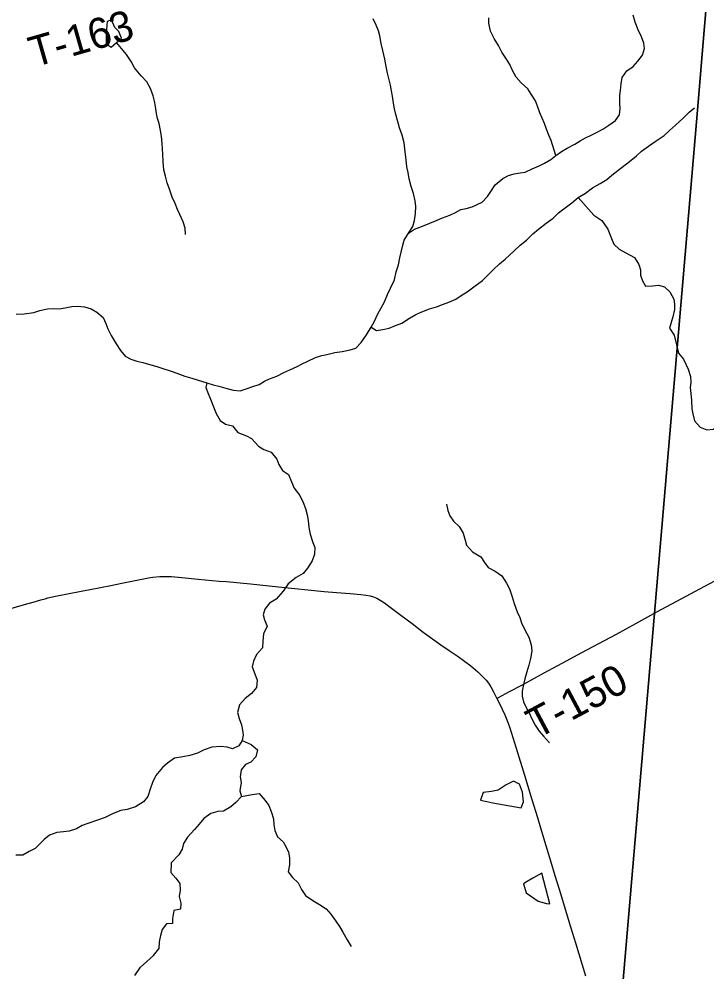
# Model space of a CAD drawing. Extents: x 0 to 1101, y 0 to 440.
# Drawn here: x 846.422 to 847.707, y 377.265 to 379.047 of the extents above; entities that cross this region are included whole.
import ezdxf

# ---------------------------------------------------------------- set-up
doc = ezdxf.new("R2010")
doc.units = 0
for name, color, linetype in [('GM_X_County_Road', 7, 'Continuous'), ('GM_X_Minor_Lake', 7, 'Continuous'), ('GM_X_Minor_River', 7, 'Continuous'), ('GM_X_State_Route', 7, 'Continuous'), ('GM_X_Township_Road', 7, 'Continuous'), ('GM_X_Township_Road_Text', 7, 'Continuous')]:
    doc.layers.add(name, color=color, linetype=linetype)

msp = doc.modelspace()

# ---------------------------------------------------------------- linework, layer by layer
at = {"layer": 'GM_X_County_Road'}
msp.add_lwpolyline([(847.5335, 377.0456), (847.6089, 377.9284), (847.6897, 378.8763), (847.7828, 379.9871), (847.8653, 380.9722), (847.896, 381.3391), (846.8323, 381.427), (846.7789, 381.4314), (846.7617, 381.4329), (846.7534, 381.4335), (845.8327, 381.5116), (845.7218, 381.5239), (845.7047, 381.5258), (845.3492, 381.569), (845.0655, 381.6042), (845.008, 381.6114), (844.8229, 381.6343), (844.8107, 381.6358), (844.7738, 381.6404), (844.7118, 381.648), (844.0658, 381.7282)], dxfattribs=at)
msp.add_lwpolyline([(850.9258, 375.8797), (850.9258, 381.1617), (850.8488, 381.1661), (850.84, 381.1666), (850.8316, 381.167), (850.794, 381.1689), (850.7928, 381.169), (849.9699, 381.2155), (849.9584, 381.2161), (849.5879, 381.237), (848.2076, 381.3203), (847.9626, 381.3347), (847.896, 381.3391), (847.8653, 380.9722), (847.7828, 379.9871), (847.6897, 378.8763), (847.6089, 377.9284), (847.5335, 377.0456), (847.5303, 377.0082), (847.4662, 376.2566), (847.7946, 376.221), (849.0627, 376.0925), (849.9034, 375.9956), (850.1463, 375.9688)], close=True, dxfattribs=at)
at = {"layer": 'GM_X_Minor_Lake'}
for points in [[(846.613, 379.0107), (846.6082, 379.0233), (846.6008, 379.031), (846.5945, 379.0452), (846.5861, 379.0419), (846.5843, 379.0195), (846.5844, 379.0002), (846.5938, 378.9943)], [(846.5938, 378.9943), (846.613, 379.0107)], [(847.3604, 377.5717), (847.3644, 377.5831), (847.3627, 377.6013), (847.3569, 377.6162), (847.3456, 377.6217), (847.3318, 377.6146), (847.3169, 377.6046), (847.3048, 377.6025), (847.2892, 377.6004), (847.2841, 377.5861), (847.2958, 377.5837), (847.3071, 377.5808)], [(847.3071, 377.5808), (847.3604, 377.5717)], [(847.3985, 377.4498), (847.3817, 377.4405), (847.3714, 377.4342), (847.3648, 377.4294), (847.3692, 377.4127), (847.3917, 377.3975), (847.4075, 377.3931), (847.4136, 377.3923)], [(847.4136, 377.3923), (847.3985, 377.4498)]]:
    msp.add_lwpolyline(points, dxfattribs=at)
at = {"layer": 'GM_X_Minor_River'}
for points in [[(847.5446, 378.9039), (847.5455, 378.9133), (847.5468, 378.9258), (847.5492, 378.9372), (847.5577, 378.9496), (847.5696, 378.9581), (847.5781, 378.9679), (847.587, 378.9792), (847.5906, 378.9916), (847.5896, 379.0019), (847.5852, 379.0133), (847.5785, 379.0267), (847.5731, 379.0408), (847.5695, 379.0541)], [(847.1498, 378.6461), (847.1579, 378.6585), (847.1607, 378.6699), (847.1625, 378.6831), (847.163, 378.6964), (847.162, 378.7071), (847.1588, 378.7204), (847.1548, 378.7333), (847.1509, 378.7482), (847.1488, 378.76), (847.1466, 378.7703), (847.1449, 378.7836), (847.1436, 378.7987), (847.1412, 378.8155), (847.138, 378.8296), (847.1329, 378.8433), (847.1289, 378.857), (847.1257, 378.8681), (847.1232, 378.8787), (847.1218, 378.8897), (847.1197, 378.9027), (847.118, 378.9126), (847.1158, 378.9228), (847.1126, 378.9358), (847.1105, 378.9457), (847.108, 378.9578), (847.1055, 378.9719), (847.1016, 378.9879), (847.0987, 379.0008), (847.0959, 379.0153), (847.0934, 379.0248), (847.0894, 379.0355), (847.0835, 379.0474)], [(847.4251, 378.7917), (847.4164, 378.8199), (847.412, 378.8299), (847.4072, 378.8406), (847.4036, 378.8512), (847.3952, 378.8715), (847.3908, 378.884), (847.3868, 378.8936), (847.379, 378.9062), (847.3723, 378.9165), (847.3603, 378.9273), (847.3506, 378.9381), (847.3436, 378.9519), (847.3389, 378.9618), (847.3326, 378.9717), (847.324, 378.9848), (847.3177, 378.997), (847.3096, 379.0104), (847.3026, 379.0241), (847.2998, 379.039), (847.2999, 379.0488)], [(846.7329, 378.6441), (846.7319, 378.6555), (846.7286, 378.6673), (846.722, 378.681), (846.718, 378.6906), (846.7136, 378.702), (846.7077, 378.7139), (846.7026, 378.7287), (846.6986, 378.7405), (846.6954, 378.7531), (846.6921, 378.7645), (846.6908, 378.7801), (846.6906, 378.7938), (846.69, 378.804), (846.689, 378.8143), (846.6877, 378.828), (846.686, 378.8386), (846.6835, 378.8512), (846.6802, 378.8607), (846.6788, 378.8702), (846.6764, 378.8831), (846.675, 378.893), (846.6725, 378.9029), (846.6674, 378.9166), (846.6604, 378.9296), (846.6499, 378.9404), (846.6372, 378.9554), (846.6313, 378.9672), (846.6224, 378.9803), (846.604, 379.003)], [(846.5437, 378.5083), (846.5565, 378.5047), (846.5671, 378.4984), (846.5791, 378.4884), (846.5838, 378.4777), (846.5878, 378.4674), (846.5941, 378.4548), (846.6034, 378.4395), (846.6112, 378.4269), (846.6201, 378.4165), (846.6306, 378.411), (846.6416, 378.4071), (846.6529, 378.4043), (846.6635, 378.4011), (846.6793, 378.3971), (846.6903, 378.3935), (846.7042, 378.3891), (846.7167, 378.3844), (846.7318, 378.3789), (846.7446, 378.3749), (846.7544, 378.3721), (846.7729, 378.3665), (846.7842, 378.363), (846.7952, 378.3602), (846.808, 378.3562), (846.8216, 378.353), (846.8352, 378.3512), (846.8478, 378.3556), (846.8584, 378.3596), (846.8702, 378.3636), (846.8802, 378.3696), (846.8897, 378.374), (846.9034, 378.3791), (846.9164, 378.3858), (846.9279, 378.3909), (846.9412, 378.3972), (846.9508, 378.402), (846.9615, 378.4071), (846.9756, 378.4138), (846.9874, 378.4178), (846.9969, 378.4195), (847.0121, 378.4235), (847.0254, 378.4252), (847.0406, 378.428), (847.0509, 378.4313), (847.0609, 378.4418), (847.0709, 378.456), (847.0798, 378.4707), (847.0857, 378.482), (847.0923, 378.4952), (847.0981, 378.5054), (847.1048, 378.5182), (847.1103, 378.5314), (847.1161, 378.5438), (847.1232, 378.5593), (847.1268, 378.574), (847.1311, 378.5872), (847.1336, 378.6001), (847.1357, 378.6111), (847.1381, 378.6216), (847.1417, 378.6334), (847.1498, 378.6461), (847.1605, 378.6536), (847.1758, 378.6594), (847.1895, 378.6649), (847.2032, 378.6708), (847.2131, 378.6752), (847.2265, 378.68), (847.2371, 378.6851), (847.2474, 378.6903), (847.2573, 378.6924), (847.2684, 378.6953), (847.2779, 378.6997), (847.2874, 378.7045), (847.2971, 378.7146), (847.3036, 378.7244), (847.3118, 378.7368), (847.3256, 378.7488), (847.3367, 378.7543), (847.3473, 378.7572), (847.358, 378.7589), (847.3678, 378.7607), (847.3804, 378.7669), (847.3938, 378.7725), (847.4037, 378.7772), (847.4155, 378.7843), (847.4251, 378.7917), (847.4358, 378.7992), (847.4462, 378.8055), (847.4607, 378.8129), (847.4706, 378.8188), (847.4805, 378.8243), (847.4908, 378.8295), (847.5008, 378.8343), (847.513, 378.841), (847.5241, 378.8484), (847.5367, 378.8573), (847.5437, 378.8678), (847.545, 378.8788), (847.5448, 378.8894), (847.5446, 378.9039)], [(847.0798, 378.4707), (847.09, 378.4641), (847.1018, 378.4662), (847.1132, 378.4687), (847.1254, 378.4739), (847.1368, 378.4783), (847.1513, 378.4872), (847.1632, 378.4942), (847.1746, 378.4993), (847.1887, 378.5048), (847.2017, 378.5088), (847.2131, 378.5128), (847.2249, 378.5172), (847.2379, 378.5231), (847.2497, 378.5309), (847.2593, 378.5368), (847.2719, 378.5462), (847.2876, 378.5581), (847.298, 378.5678), (847.3076, 378.5775), (847.3195, 378.5887), (847.3303, 378.5977), (847.3472, 378.613), (847.3583, 378.6238), (847.3702, 378.6335), (847.3821, 378.6448), (847.3928, 378.6537), (847.4067, 378.6653), (847.4197, 378.6746), (847.4297, 378.6843), (847.4446, 378.6955), (847.4546, 378.7029), (847.4668, 378.713), (847.4802, 378.7211), (847.4936, 378.7308), (847.5078, 378.739), (847.52, 378.7468), (847.5296, 378.755), (847.5441, 378.7661), (847.5595, 378.7777), (847.5756, 378.7907), (847.5852, 378.7997), (847.5982, 378.809), (847.6108, 378.8176), (847.6277, 378.8287), (847.6376, 378.8381), (847.6488, 378.8481), (847.6626, 378.8612), (847.6741, 378.8728), (847.6841, 378.881)], [(847.4668, 378.713), (847.4959, 378.6803), (847.5109, 378.6699), (847.5221, 378.6538), (847.5287, 378.6362), (847.5331, 378.6259), (847.5435, 378.6163), (847.556, 378.6097), (847.5717, 378.6011), (847.5803, 378.5877), (847.5832, 378.5778), (847.5834, 378.5675), (847.5867, 378.5569), (847.5926, 378.5473), (847.6059, 378.5479), (847.6165, 378.5492), (847.6282, 378.546), (847.6379, 378.5364), (847.6453, 378.523), (847.6467, 378.5135), (847.6465, 378.5037), (847.6437, 378.4897), (847.6373, 378.4685), (847.6459, 378.4559)], [(846.4162, 378.4949), (846.4313, 378.4958), (846.4496, 378.4982), (846.4606, 378.5015), (846.4751, 378.5051), (846.4853, 378.5053), (846.4967, 378.5048), (846.5081, 378.5065), (846.5202, 378.5094), (846.5305, 378.51), (846.5437, 378.5083)], [(847.6459, 378.4559), (847.6541, 378.422), (847.6634, 378.4109), (847.6722, 378.3921), (847.6766, 378.3784), (847.6771, 378.3674), (847.6762, 378.3575), (847.6772, 378.3465), (847.6785, 378.3336), (847.6794, 378.318), (847.6812, 378.3085), (847.684, 378.2956), (847.6944, 378.2836), (847.7069, 378.2785), (847.7199, 378.2798), (847.7303, 378.2918), (847.7402, 378.2928), (847.7682, 378.3329)], [(846.7729, 378.3665), (846.7709, 378.3575), (846.7749, 378.3464), (846.7797, 378.3357), (846.7851, 378.3216), (846.7903, 378.3094), (846.7977, 378.296), (846.8074, 378.2894), (846.8203, 378.2862), (846.8307, 378.2735), (846.8465, 378.2672), (846.8563, 378.2625), (846.8694, 378.2479), (846.8791, 378.2417), (846.8927, 378.237), (846.9035, 378.2239), (846.9072, 378.2136), (846.9142, 378.2025), (846.9251, 378.1952), (846.931, 378.1814), (846.9361, 378.1692), (846.9465, 378.1558), (846.9524, 378.1428), (846.9572, 378.1317), (846.9604, 378.1196), (846.9621, 378.1093), (846.9631, 378.096), (846.9659, 378.0834), (846.971, 378.0678), (846.9743, 378.0583), (846.9741, 378.0461), (846.9694, 378.0337), (846.9609, 378.0201), (846.9528, 378.01), (846.9398, 378.0022), (846.9248, 377.9907), (846.9155, 377.9772), (846.9024, 377.9622), (846.8895, 377.9544), (846.8813, 377.9435), (846.8782, 377.9329), (846.8807, 377.9234), (846.8854, 377.9116), (846.8784, 377.8973), (846.8775, 377.8832), (846.8769, 377.8711), (846.8654, 377.8587), (846.8599, 377.8459), (846.8574, 377.8353), (846.8622, 377.8224), (846.8669, 377.8105), (846.8656, 377.7969), (846.856, 377.7853), (846.8445, 377.7759), (846.8337, 377.7643), (846.8297, 377.75), (846.833, 377.7389), (846.8373, 377.7267), (846.8395, 377.7172), (846.8405, 377.7077), (846.8388, 377.6975), (846.8322, 377.6877), (846.8204, 377.6822), (846.8106, 377.6854), (846.7985, 377.6867), (846.7818, 377.685), (846.7677, 377.6803), (846.7551, 377.674), (846.741, 377.6697), (846.7277, 377.6668), (846.7125, 377.6644), (846.6991, 377.6551), (846.6895, 377.6472), (846.6776, 377.6322), (846.6713, 377.6194), (846.667, 377.6066), (846.6626, 377.593), (846.6541, 377.5829), (846.6392, 377.5736), (846.624, 377.5689), (846.6118, 377.5668), (846.5977, 377.5609), (846.5825, 377.5539), (846.568, 377.5488), (846.5505, 377.5422), (846.5398, 377.5386), (846.5291, 377.5327), (846.5154, 377.5283), (846.5048, 377.5269), (846.4922, 377.5256), (846.4785, 377.5205), (846.4685, 377.5123), (846.4516, 377.4958), (846.4406, 377.4903), (846.4287, 377.4832), (846.4158, 377.4831)], [(847.2203, 378.1398), (847.2228, 378.1276), (847.2268, 378.1177), (847.2339, 378.1081), (847.2443, 378.0977), (847.2517, 378.0855), (847.2557, 378.0725), (847.2579, 378.063), (847.2694, 378.0503), (847.2845, 378.041), (847.2919, 378.0306), (847.2986, 378.0211), (847.3118, 378.014), (847.3238, 378.0055), (847.3327, 377.9917), (847.3386, 377.981), (847.3433, 377.9662), (847.3473, 377.954), (847.3527, 377.9383), (847.3575, 377.9277), (847.3608, 377.9174), (847.3667, 377.9044), (847.3744, 377.8906), (847.3788, 377.8765), (847.3801, 377.8655), (847.3773, 377.8511), (847.3744, 377.8386), (847.3705, 377.8258), (847.3669, 377.8129), (847.3645, 377.8024), (847.362, 377.7899), (847.3622, 377.7804), (847.3644, 377.7701), (847.3692, 377.7594), (847.3751, 377.7495), (847.3806, 377.7369), (847.3861, 377.7262), (847.3939, 377.7154), (847.4021, 377.7058), (847.4129, 377.6935)], [(846.8388, 377.6975), (846.8558, 377.6904), (846.8674, 377.68), (846.8641, 377.6672), (846.8549, 377.6574), (846.8446, 377.6526), (846.8365, 377.6425), (846.8348, 377.6296), (846.8369, 377.619), (846.8344, 377.6038), (846.8377, 377.5928), (846.8575, 377.5967), (846.8704, 377.5988), (846.8819, 377.5857), (846.8886, 377.5761), (846.893, 377.5651), (846.8974, 377.5514), (846.898, 377.5403), (846.8997, 377.5293), (846.9048, 377.5175), (846.9153, 377.5079), (846.9209, 377.4983), (846.9253, 377.4887), (846.9274, 377.4785), (846.9272, 377.4652), (846.9244, 377.4523), (846.933, 377.4416), (846.9434, 377.4312), (846.9497, 377.419), (846.9571, 377.4079), (846.9706, 377.3982), (846.983, 377.3912), (846.9958, 377.383), (847.0047, 377.3727), (847.014, 377.36), (847.0203, 377.3501), (847.0266, 377.3393), (847.0348, 377.3248), (847.0425, 377.3122)], [(846.8377, 377.5928), (846.8269, 377.5816), (846.8173, 377.5734), (846.8036, 377.5656), (846.793, 377.5646), (846.7804, 377.561), (846.767, 377.5517), (846.7585, 377.5412), (846.7496, 377.5311), (846.7366, 377.5168), (846.7292, 377.5048), (846.7264, 377.4946), (846.7202, 377.4841), (846.7059, 377.4687), (846.7053, 377.4509), (846.7146, 377.4401), (846.7221, 377.4305), (846.7226, 377.418), (846.721, 377.4059), (846.7242, 377.3937), (846.7233, 377.3823), (846.7107, 377.3795), (846.7086, 377.3647), (846.7085, 377.3552), (846.6975, 377.3546), (846.689, 377.3445), (846.6858, 377.3328), (846.6838, 377.3214), (846.6829, 377.3078)], [(846.6382, 377.2583), (846.6488, 377.2737), (846.6608, 377.2842), (846.6728, 377.2958), (846.6829, 377.3078)]]:
    msp.add_lwpolyline(points, dxfattribs=at)
at = {"layer": 'GM_X_State_Route'}
msp.add_lwpolyline([(846.4017, 377.9431), (846.432, 377.9517), (846.4482, 377.9564), (846.4621, 377.9606), (846.4703, 377.9628), (846.4756, 377.9642), (846.4901, 377.9676), (846.512, 377.9721), (846.5376, 377.9769), (846.5547, 377.9801), (846.593, 377.9876), (846.6136, 377.992), (846.6385, 377.9971), (846.6634, 378.0018), (846.672, 378.0031), (846.6849, 378.0043), (846.696, 378.0046), (846.7065, 378.0042), (846.7262, 378.0025), (846.7565, 377.9995), (846.796, 377.9959), (846.8096, 377.9947), (846.8542, 377.9903), (846.9067, 377.9852), (846.9917, 377.9765), (847.015, 377.9744), (847.0405, 377.9723), (847.0604, 377.9704), (847.0698, 377.9693), (847.0777, 377.9679), (847.0842, 377.9662), (847.0904, 377.9637), (847.0969, 377.9602), (847.1048, 377.9549), (847.1176, 377.9454), (847.1355, 377.9321), (847.1562, 377.9162), (847.1772, 377.9005), (847.2101, 377.8765), (847.2255, 377.8658), (847.2351, 377.8595), (847.2424, 377.8546), (847.2544, 377.8459), (847.2659, 377.8371), (847.279, 377.8258), (847.2885, 377.8169), (847.2948, 377.8102), (847.2989, 377.8049), (847.3033, 377.7983), (847.3086, 377.7885), (847.3147, 377.7762), (847.3194, 377.7668), (847.3296, 377.7458), (847.3348, 377.7332), (847.3384, 377.7233), (847.3507, 377.6836), (847.3661, 377.6331), (847.3803, 377.5874), (847.3907, 377.5536), (847.3964, 377.5345), (847.4063, 377.5013), (847.4151, 377.4728), (847.4233, 377.4455), (847.4311, 377.4199), (847.4523, 377.3495), (847.4615, 377.3194), (847.4806, 377.2577)], dxfattribs=at)
at = {"layer": 'GM_X_Township_Road'}
msp.add_line((847.6118, 377.937), (847.6127, 377.9374), dxfattribs=at)
for points in [[(847.6127, 377.9374), (847.6509, 377.9579), (847.6848, 377.9761), (847.722, 377.996)], [(847.3147, 377.7762), (847.3167, 377.7773), (847.3398, 377.7896), (847.3616, 377.8013), (847.4031, 377.824), (847.4446, 377.8464), (847.4736, 377.862), (847.495, 377.8733), (847.538, 377.8968), (847.5746, 377.9166), (847.6083, 377.9351), (847.6118, 377.937)]]:
    msp.add_lwpolyline(points, dxfattribs=at)

# ---------------------------------------------------------------- texts
at = {"layer": 'GM_X_Township_Road_Text'}
for s, rotation, p in [('T-163', 15.9454, (846.4497, 378.9562)), ('T-150', 28.0726, (847.3899, 377.6998))]:
    msp.add_text(s, height=0.05682, rotation=rotation, dxfattribs=at).set_placement(p)

doc.saveas('drawing.dxf')
